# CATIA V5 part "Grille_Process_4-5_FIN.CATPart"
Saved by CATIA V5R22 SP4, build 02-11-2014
Part number: Grille
Bounding box of the stored display mesh (mm): x -153.245 to -100.002, y -313 to 313, z 227 to 413
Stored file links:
  C:\DATA\Car_ASSY\教育モデル\4_SUR\Grille_Process_4-5_FIN.CATPart
  C:\DATA\Car_ASSY\教育モデル\4_SUR\Grille_FIN.CATPart
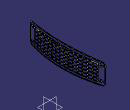
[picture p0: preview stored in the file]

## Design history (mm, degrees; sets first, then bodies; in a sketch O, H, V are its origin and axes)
Set1 "Danmen"
  Intersect1: ToIntersect1 Sweep1, ToIntersect2 Pad1
Set2 "Boss_Danmen"
  Sketch1 on Plane1, origin (-185, 0, 0), H (0, 1, 0), V (0, 0, 1)
    circle A1 centre (-280, 370) radius 6
    circle A2 centre (-280, 260) radius 6
    circle A3 centre (280, 370) radius 6
    circle A4 centre (280, 260) radius 6
    circle A5 centre (-280, 370) radius 9
    point P1 (-280, 370)
    circle A6 centre (-280, 260) radius 9
    point P2 (-280, 260)
    circle A7 centre (280, 260) radius 9
    point P3 (280, 260)
    circle A8 centre (280, 370) radius 9
    point P4 (280, 370)
    radius A5 = 9
    radius A6 = 9
    radius A7 = 9
    radius A8 = 9
    distance P4 V = 280
    distance H P4 = 370
    radius A3 = 6
    distance P3 P4 = 110
    distance V P3 = 280
    radius A4 = 6
    radius A2 = 6
    radius A1 = 6
    distance P1 V = 280
    distance P2 V = 280
    distance H P2 = 260
    distance P2 P1 = 110
    concentricity: P1 A1, P2 A2, P3 A4, P4 A3
  Plane1: type Offset, RefPlane yz-plane, Offset -185
Set3 "Front"
  Point1: (-1100, 0, 300)
  Circle1: type CtrRad, Start -30, End 30, Radius 1000, FirstDirection (1, 0, 0), Center Point1, Support xy-plane
  Circle2: type CtrRad, Start 165, End 195, Radius 1000, FirstDirection (-1, 0, 0), Center Point1, Support zx-plane
  Sweep1: type Unspec, Profile Circle2, Guide Circle1
Body1 (main body)
Body2
  Sketch2 on yz-plane, origin (0, 0, 0), H (0, 1, 0), V (0, 0, 1)
    point P1 (0.0002, 410)
    construction line L1 (0.0002, 410) -> (310, 410)
    point P2 (310, 410)
    line L2 (310, 372.6426) -> (310, 250)
    point P3 (310, 230)
    line L3 (290, 230) -> (0, 230)
    point P4 (0, 230)
    circle A1 centre (280, 370) radius 8
    circle A2 centre (280, 260) radius 8
    spline S1 through (0.0002, 410) (184.2802, 403.8794) (310, 390)
    arc A3 centre (290, 250) radius 20 from (290, 230) to (310, 250) ccw
    point P5 (290, 230)
    point P6 (310, 250)
    arc A4 centre (290, 372.6426) radius 20 from (292.7155, 392.4574) to (310, 372.6426) cw
    point P8 (292.7155, 392.4574)
    point P9 (310, 372.6426)
    offsetcurve C1
    point P11 (0.0002, 390)
    point P12 (290.0001, 372.6425)
    construction line L4 (0.0002, 410) -> (0.0002, 390)
    point P13 (0.0002, 410)
    construction line L5 through (0.0002, 410) direction (-1, 0)
    construction line L6 (292.7155, 392.4574) -> (290.0001, 372.6425)
    construction line L7 through (292.7155, 392.4574) direction (0.9907, -0.1358)
    line L8 (260, 376.4843) -> (260, 255)
    point P14 (257.373, 372.6426)
    point P15 (257.373, 250)
    construction line L9 (310, 372.6426) -> (257.373, 372.6426)
    construction line L10 (310, 250) -> (257.373, 250)
    line L11 (255, 250) -> (0, 250)
    point P16 (290, 250)
    point P17 (0, 250)
    construction line L12 (290, 230) -> (290, 250)
    construction line L13 (0, 230) -> (0, 250)
    point P18 (260, 376.4843)
    point P19 (260, 250)
    line L14 (272, 370) -> (260, 370)
    point P20 (272, 370)
    point P21 (260, 370)
    line L15 (288, 370) -> (310, 370)
    point P22 (288, 370)
    point P23 (310, 370)
    line L16 (288, 260) -> (310, 260)
    point P24 (288, 260)
    point P25 (310, 260)
    line L17 (272, 260) -> (260, 260)
    point P26 (272, 260)
    point P27 (260, 260)
    line L18 (260, 275) -> (0, 275)
    point P28 (260, 275)
    point P29 (0, 275)
    construction line L19 (260, 250) -> (260, 275)
    construction line L20 (0, 250) -> (0, 275)
    line L21 (260, 300) -> (0, 300)
    point P30 (260, 300)
    point P31 (0, 300)
    construction line L22 (260, 275) -> (260, 300)
    construction line L23 (0, 275) -> (0, 300)
    line L24 (260, 325) -> (0, 325)
    point P32 (260, 325)
    point P33 (0, 325)
    construction line L25 (260, 300) -> (260, 325)
    construction line L26 (0, 300) -> (0, 325)
    line L27 (260, 350) -> (0, 350)
    point P34 (260, 350)
    point P35 (0, 350)
    construction line L28 (260, 325) -> (260, 350)
    construction line L29 (0, 325) -> (0, 350)
    line L30 (260, 375) -> (0, 375)
    point P36 (260, 375)
    point P37 (0, 375)
    construction line L31 (260, 350) -> (260, 375)
    construction line L32 (0, 350) -> (0, 375)
    arc A5 centre (255, 255) radius 5 from (260, 255) to (255, 250) cw
    point P38 (260, 255)
    point P39 (255, 250)
    line L33 (17.5, 250) -> (17.5, 389.9532)
    point P41 (17.5, 250)
    point P42 (17.5, 389.9532)
    line L34 (52.5, 250) -> (52.5, 389.5709)
    point P43 (52.5, 250)
    point P44 (52.5, 389.5709)
    line L35 (87.5, 250) -> (87.5, 388.769)
    point P45 (87.5, 250)
    point P46 (87.5, 388.769)
    line L36 (122.5, 250) -> (122.5, 387.4859)
    point P47 (122.5, 250)
    point P48 (122.5, 387.4859)
    line L37 (157.5, 250) -> (157.5, 385.6484)
    point P49 (157.5, 250)
    point P50 (157.5, 385.6484)
    line L38 (192.5, 250) -> (192.5, 383.1854)
    point P51 (192.5, 250)
    point P52 (192.5, 383.1854)
    line L39 (227.5, 250) -> (227.5, 380.0419)
    point P53 (227.5, 250)
    point P54 (227.5, 380.0419)
    point P55 (-0.0002, 410)
    point P56 (-310, 410)
    construction line L40 (-0.0002, 410) -> (-310, 410)
    point P57 (-310, 230)
    point P58 (0, 230)
    point P59 (-290, 230)
    point P60 (-310, 250)
    point P62 (-292.7155, 392.4574)
    point P63 (-310, 372.6426)
    point P65 (-0.0002, 390)
    point P66 (-290.0001, 372.6425)
    point P67 (-257.373, 372.6426)
    point P68 (-257.373, 250)
    point P69 (-290, 250)
    point P70 (0, 250)
    point P71 (-260, 376.4843)
    point P72 (-260, 250)
    point P73 (-272, 370)
    point P74 (-260, 370)
    point P75 (-288, 370)
    point P76 (-310, 370)
    point P77 (-288, 260)
    point P78 (-310, 260)
    point P79 (-272, 260)
    point P80 (-260, 260)
    point P81 (-260, 275)
    point P82 (0, 275)
    point P83 (-260, 300)
    point P84 (0, 300)
    point P85 (-260, 325)
    point P86 (0, 325)
    point P87 (-260, 350)
    point P88 (0, 350)
    point P89 (-260, 375)
    point P90 (0, 375)
    point P91 (-260, 255)
    point P92 (-255, 250)
    point P94 (-17.5, 250)
    point P95 (-17.5, 389.9532)
    point P96 (-52.5, 250)
    point P97 (-52.5, 389.5709)
    point P98 (-87.5, 250)
    point P99 (-87.5, 388.769)
    point P100 (-122.5, 250)
    point P101 (-122.5, 387.4859)
    point P102 (-157.5, 250)
    point P103 (-157.5, 385.6484)
    point P104 (-192.5, 250)
    point P105 (-192.5, 383.1854)
    point P106 (-227.5, 250)
    point P107 (-227.5, 380.0419)
    line L41 (-310, 372.6426) -> (-310, 250)
    line L42 (-290, 230) -> (0, 230)
    circle A6 centre (-280, 370) radius 8
    circle A7 centre (-280, 260) radius 8
    spline S2 through (-0.0002, 410) (-184.2802, 403.8794) (-310, 390)
    arc A8 centre (-290, 250) radius 20 from (-290, 230) to (-310, 250) cw
    arc A9 centre (-290, 372.6426) radius 20 from (-292.7155, 392.4574) to (-310, 372.6426) ccw
    offsetcurve C2
    line L43 (-260, 376.4843) -> (-260, 255)
    line L44 (-255, 250) -> (0, 250)
    line L45 (-272, 370) -> (-260, 370)
    line L46 (-288, 370) -> (-310, 370)
    line L47 (-288, 260) -> (-310, 260)
    line L48 (-272, 260) -> (-260, 260)
    line L49 (-260, 275) -> (0, 275)
    line L50 (-260, 300) -> (0, 300)
    line L51 (-260, 325) -> (0, 325)
    line L52 (-260, 350) -> (0, 350)
    line L53 (-260, 375) -> (0, 375)
    arc A10 centre (-255, 255) radius 5 from (-260, 255) to (-255, 250) ccw
    line L54 (-17.5, 250) -> (-17.5, 389.9532)
    line L55 (-52.5, 250) -> (-52.5, 389.5709)
    line L56 (-87.5, 250) -> (-87.5, 388.769)
    line L57 (-122.5, 250) -> (-122.5, 387.4859)
    line L58 (-157.5, 250) -> (-157.5, 385.6484)
    line L59 (-192.5, 250) -> (-192.5, 383.1854)
    line L60 (-227.5, 250) -> (-227.5, 380.0419)
    point P108 (0.0002, 410)
    point P109 (310, 390)
    point P110 (184.2802, 403.8794)
    point P111 (-0.0002, 410)
    point P112 (-310, 390)
    point P113 (-184.2802, 403.8794)
    distance H L3 = 230
    distance L2 V = 310
    distance P109 L1 = 20
    distance P2 P3 = 180
    distance V P110 = 184.2802
    distance P110 P109 V = 13.8794
    distance P108 P4 = 180
    radius A3 = 20
    radius A4 = 20
    distance L2 L8 = 50
    distance L3 L11 = 20
    distance L16 L3 = 30
    distance L15 L16 = 110
    distance A1 L15 = 8
    distance A1 L15 = 8
    distance A1 L2 = 38
    distance A2 L16 = 8
    distance A2 L16 = 8
    distance L2 A2 = 38
    distance L11 L18 = 25
    distance L18 L21 = 25
    distance L21 L24 = 25
    distance L24 L27 = 25
    distance L27 L30 = 25
    radius A5 = 5
    distance V L33 = 17.5
    distance L33 L34 = 35
    distance L34 L35 = 35
    distance L35 L36 = 35
    distance L36 L37 = 35
    distance L37 L38 = 35
    distance L38 L39 = 35
    horizontal: L1 H, L3 H, L14 H, L15 H, L16 H, L17 H
    vertical: L2 V, L33 V, L34 V, L35 V, L36 V, L37 V, L38 V, L39 V
    coincidence: P4 V, P108 P1, P109 L2, P2 L2, L3 P3, L2 P3, P108 P13, P12 C1, P16 L11, P20 A1, P21 L8, P22 L14, P22 A1, P23 L2, P24 A2, P25 L2, P26 L16, P26 A2, P27 L8, L8 P19, L11 P19, P41 L11, P42 C1, P43 L11, P44 C1, P45 L11, P46 C1, P47 L11, P48 C1, P49 L11, P50 C1, P51 L11, P52 C1, P53 L11, P54 C1, P4 P58, P17 P70, P29 P82, P31 P84, P33 P86, P35 P88, P37 P90
    tangency: A3 L3, A3 L2, A4 S1, A4 L2, L5 S1, L7 S1, A5 L8, A5 L11
    perpendicularity: L4 L5, L6 L7, L9 L2, L9 L8, L10 L2, L10 L8, L12 L3, L12 L11, L13 L3, L13 L11, L19 L11, L19 L18, L20 L11, L20 L18, L22 L18, L22 L21, L23 L18, L23 L21, L25 L21, L25 L24, L26 L21, L26 L24, L28 L24, L28 L27, L29 L24, L29 L27, L31 L27, L31 L30, L32 L27, L32 L30
    symmetry: P1 P55 V, P2 P56 V, L1 L40 V, P3 P57 V, P4 P58 V, P5 P59 V, P6 P60 V, P8 P62 V, P9 P63 V, P11 P65 V, P12 P66 V, P14 P67 V, P15 P68 V, P16 P69 V, P17 P70 V, P18 P71 V, P19 P72 V, P20 P73 V, P21 P74 V, P22 P75 V, P23 P76 V, P24 P77 V, P25 P78 V, P26 P79 V, P27 P80 V, P28 P81 V, P29 P82 V, P30 P83 V, P31 P84 V, P32 P85 V, P33 P86 V, P34 P87 V, P35 P88 V, P36 P89 V, P37 P90 V, P38 P91 V, P39 P92 V, P41 P94 V, P42 P95 V, P43 P96 V, P44 P97 V, P45 P98 V, P46 P99 V, P47 P100 V, P48 P101 V, P49 P102 V, P50 P103 V, P51 P104 V, P52 P105 V, P53 P106 V, P54 P107 V, L2 L41 V, L3 L42 V, A1 A6 V, A2 A7 V, S1 S2 V, A3 A8 V, A4 A9 V, C1 C2 V, L8 L43 V, L11 L44 V, L14 L45 V, L15 L46 V, L16 L47 V, L17 L48 V, L18 L49 V, L21 L50 V, L24 L51 V, L27 L52 V, L30 L53 V, A5 A10 V, L33 L54 V, L34 L55 V, L35 L56 V, L36 L57 V, L37 L58 V, L38 L59 V, L39 L60 V, P108 P111 V, P109 P112 V, P110 P113 V
  Pad1: profile Sketch2, direction (-1, 0, 0), length 350, thin wall 6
